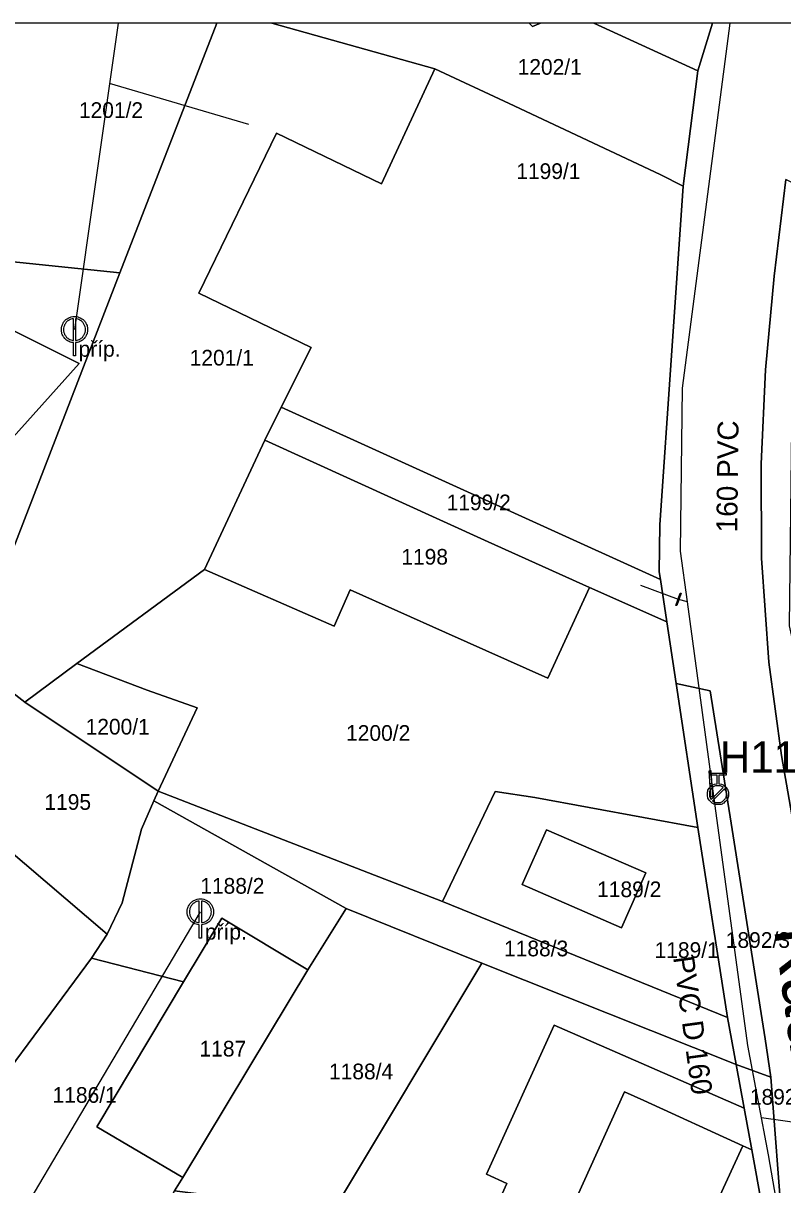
# Model space of a CAD drawing. Extents: x -559956 to -559707, y -1077221 to -1076919.
# Drawn here: x -559895.5 to -559822.9, y -1077029.9 to -1076918.8 of the extents above; entities that cross this region are included whole.
import ezdxf

# ---------------------------------------------------------------- set-up
doc = ezdxf.new("R2010")
doc.units = 0
for name, color, linetype in [('Armatura vodovodní', 7, 'Continuous'), ('Hydrant', 7, 'Continuous'), ('Kanalizační přípojka', 7, 'Continuous'), ('Kanalizační šachta', 7, 'Continuous'), ('Označení hydrantu', 7, 'Continuous'), ('Parcela-polygon', 7, 'Continuous'), ('Parcela-text', 7, 'Continuous'), ('Popis šachty', 7, 'Continuous'), ('Vodovodní přípojka', 7, 'Continuous'), ('Vodovodní řad', 7, 'Continuous'), ('Řad vodovodní označení', 7, 'Continuous'), ('Řad vodovodní popis', 7, 'Continuous')]:
    doc.layers.add(name, color=color, linetype=linetype)

msp = doc.modelspace()

# ---------------------------------------------------------------- linework, layer by layer
at = {"layer": 'Armatura vodovodní'}
for points in [[(-559832.58, -1076973.29), (-559832.99, -1076974.47), (-559833.07, -1076974.45), (-559832.66, -1076973.27), (-559832.58, -1076973.29)], [(-559829.74, -1076990.25), (-559829.57, -1076992.75), (-559829.72, -1076992.76), (-559829.89, -1076990.26), (-559829.74, -1076990.25)]]:
    msp.add_lwpolyline(points, dxfattribs=at)
at = {"layer": 'Hydrant'}
for points in [[(-559829.14, -1076991.5), (-559829.14, -1076990.69), (-559829.83, -1076990.69), (-559829.83, -1076990.5), (-559828.26, -1076990.5), (-559828.27, -1076990.69), (-559828.95, -1076990.69), (-559828.95, -1076991.51)], [(-559829.69, -1076993.01), (-559828.54, -1076991.86)], [(-559828.41, -1076992), (-559829.56, -1076993.14)]]:
    msp.add_lwpolyline(points, dxfattribs=at)
for points in [[(-559828.95, -1076991.51), (-559828.6, -1076991.54), (-559828.34, -1076991.8), (-559828.05, -1076992.09), (-559828.05, -1076992.5), (-559828.05, -1076992.92), (-559828.34, -1076993.21), (-559828.64, -1076993.5), (-559829.05, -1076993.5), (-559829.47, -1076993.5), (-559829.76, -1076993.21), (-559830.05, -1076992.92), (-559830.05, -1076992.5), (-559830.05, -1076992.09), (-559829.76, -1076991.79), (-559829.5, -1076991.53), (-559829.14, -1076991.5)], [(-559828.54, -1076991.86), (-559828.76, -1076991.69), (-559829.05, -1076991.69), (-559829.39, -1076991.69), (-559829.63, -1076991.92), (-559829.86, -1076992.16), (-559829.86, -1076992.5), (-559829.87, -1076992.79), (-559829.69, -1076993.01)], [(-559829.56, -1076993.14), (-559829.34, -1076993.31), (-559829.05, -1076993.31), (-559828.72, -1076993.31), (-559828.48, -1076993.08), (-559828.24, -1076992.84), (-559828.24, -1076992.5), (-559828.24, -1076992.21), (-559828.41, -1076992)]]:
    msp.add_open_spline(points, degree=3, dxfattribs=at)
at = {"layer": 'Kanalizační přípojka'}
for p, q in [((-559886.39, -1076918.77), (-559890.56, -1076948.07)), ((-559873.9, -1076928.46), (-559887.22, -1076924.55))]:
    msp.add_line(p, q, dxfattribs=at)
msp.add_lwpolyline([(-559908.57, -1077054.77), (-559908.02, -1077053.62), (-559878.53, -1077003.76)], dxfattribs=at)
at = {"layer": 'Kanalizační šachta'}
for points in [[(-559890.66, -1076949.11), (-559890.66, -1076947.04)], [(-559890.46, -1076947.04), (-559890.46, -1076949.11)], [(-559890.46, -1076949.32), (-559890.46, -1076950.57), (-559890.66, -1076950.57), (-559890.66, -1076949.32)], [(-559878.63, -1077004.79), (-559878.63, -1077002.72)], [(-559878.42, -1077002.72), (-559878.42, -1077004.79)], [(-559878.42, -1077005), (-559878.42, -1077006.26), (-559878.63, -1077006.26), (-559878.63, -1077005)]]:
    msp.add_lwpolyline(points, dxfattribs=at)
for points in [[(-559890.66, -1076949.32), (-559890.92, -1076949.3), (-559891.18, -1076949.16), (-559891.48, -1076948.99), (-559891.65, -1076948.7), (-559891.81, -1076948.4), (-559891.81, -1076948.07), (-559891.81, -1076947.75), (-559891.64, -1076947.45), (-559891.48, -1076947.15), (-559891.18, -1076946.99), (-559890.88, -1076946.82), (-559890.56, -1076946.82), (-559890.25, -1076946.82), (-559889.95, -1076946.99), (-559889.65, -1076947.15), (-559889.48, -1076947.45), (-559889.31, -1076947.75), (-559889.31, -1076948.07), (-559889.31, -1076948.4), (-559889.48, -1076948.7), (-559889.64, -1076948.99), (-559889.94, -1076949.16), (-559890.2, -1076949.3), (-559890.46, -1076949.32)], [(-559890.66, -1076947.04), (-559890.86, -1076947.05), (-559891.08, -1076947.17), (-559891.33, -1076947.3), (-559891.47, -1076947.55), (-559891.6, -1076947.8), (-559891.6, -1076948.07), (-559891.6, -1076948.34), (-559891.47, -1076948.59), (-559891.33, -1076948.84), (-559891.08, -1076948.97), (-559890.87, -1076949.09), (-559890.66, -1076949.11)], [(-559890.46, -1076949.11), (-559890.25, -1076949.09), (-559890.04, -1076948.97), (-559889.79, -1076948.84), (-559889.66, -1076948.59), (-559889.52, -1076948.34), (-559889.52, -1076948.07), (-559889.52, -1076947.8), (-559889.66, -1076947.55), (-559889.8, -1076947.3), (-559890.05, -1076947.17), (-559890.26, -1076947.05), (-559890.46, -1076947.04)], [(-559878.63, -1077005), (-559878.89, -1077004.99), (-559879.15, -1077004.84), (-559879.45, -1077004.68), (-559879.61, -1077004.38), (-559879.78, -1077004.08), (-559879.78, -1077003.76), (-559879.78, -1077003.43), (-559879.61, -1077003.13), (-559879.44, -1077002.83), (-559879.14, -1077002.67), (-559878.84, -1077002.51), (-559878.53, -1077002.51), (-559878.21, -1077002.51), (-559877.91, -1077002.67), (-559877.61, -1077002.83), (-559877.45, -1077003.13), (-559877.28, -1077003.43), (-559877.28, -1077003.76), (-559877.28, -1077004.08), (-559877.44, -1077004.38), (-559877.61, -1077004.68), (-559877.9, -1077004.84), (-559878.17, -1077004.99), (-559878.42, -1077005)], [(-559878.63, -1077002.72), (-559878.83, -1077002.74), (-559879.04, -1077002.85), (-559879.29, -1077002.99), (-559879.43, -1077003.24), (-559879.57, -1077003.49), (-559879.57, -1077003.76), (-559879.57, -1077004.03), (-559879.43, -1077004.27), (-559879.3, -1077004.52), (-559879.05, -1077004.66), (-559878.83, -1077004.78), (-559878.63, -1077004.79)], [(-559878.42, -1077004.79), (-559878.22, -1077004.78), (-559878, -1077004.66), (-559877.76, -1077004.52), (-559877.62, -1077004.27), (-559877.48, -1077004.03), (-559877.48, -1077003.76), (-559877.48, -1077003.49), (-559877.62, -1077003.24), (-559877.77, -1077002.99), (-559878.01, -1077002.85), (-559878.23, -1077002.74), (-559878.42, -1077002.72)]]:
    msp.add_open_spline(points, degree=3, dxfattribs=at)
at = {"layer": 'Parcela-polygon'}
for p, q in [((-559876.97, -1076918.77), (-559898.19, -1076918.77)), ((-559871.69, -1076918.77), (-559876.97, -1076918.77)), ((-559847.1, -1076918.77), (-559871.69, -1076918.77)), ((-559846.01, -1076918.77), (-559847.1, -1076918.77)), ((-559840.92, -1076918.77), (-559846.01, -1076918.77)), ((-559829.56, -1076918.77), (-559840.92, -1076918.77)), ((-559819.59, -1076918.77), (-559829.56, -1076918.77))]:
    msp.add_line(p, q, dxfattribs=at)
for points in [[(-559898.19, -1076918.77), (-559898.32, -1076921.1), (-559898.47, -1076923.82), (-559899.79, -1076923.81), (-559900.02, -1076928.91), (-559901.08, -1076931.24), (-559902.28, -1076931.69), (-559899.85, -1076941.23), (-559886.22, -1076942.65), (-559876.97, -1076918.77)], [(-559876.97, -1076918.77), (-559886.22, -1076942.65), (-559900.64, -1076979.86), (-559897.77, -1076981.82), (-559895.32, -1076983.7), (-559890.33, -1076980.02), (-559878.13, -1076971.03), (-559872.38, -1076958.66), (-559870.8, -1076955.49), (-559867.94, -1076949.78), (-559878.66, -1076944.59), (-559871.24, -1076929.28), (-559861.21, -1076934.12), (-559856.1, -1076923.13), (-559871.69, -1076918.77)], [(-559871.69, -1076918.77), (-559856.1, -1076923.13), (-559849.01, -1076926.45), (-559834.56, -1076933.23), (-559832.36, -1076934.35), (-559830.97, -1076923.33), (-559840.92, -1076918.77)], [(-559829.56, -1076918.77), (-559830.97, -1076923.33), (-559832.36, -1076934.35), (-559834.59, -1076966.73), (-559834.66, -1076971.24), (-559834.55, -1076971.98), (-559833.93, -1076976.03), (-559833.04, -1076981.92), (-559829.78, -1076982.61), (-559827.8, -1076995.29), (-559824.54, -1077015.89), (-559823.98, -1077019.58), (-559822.89, -1077034.16), (-559824.42, -1077051.06), (-559826.97, -1077064.1), (-559830.26, -1077074.01), (-559839.63, -1077092.62), (-559840.88, -1077095.88), (-559842.14, -1077099.15), (-559851.55, -1077116.77), (-559853.81, -1077121)], [(-559846.01, -1076918.77), (-559846.77, -1076919.08), (-559847.1, -1076918.77)], [(-559847.1, -1076918.77), (-559846.77, -1076919.08), (-559846.01, -1076918.77)], [(-559840.92, -1076918.77), (-559830.97, -1076923.33), (-559829.56, -1076918.77)], [(-559821.27, -1076998.68), (-559822.96, -1076988.81), (-559824.18, -1076979.89), (-559824.89, -1076969.92), (-559824.93, -1076960.91), (-559824.5, -1076951.91), (-559823.69, -1076942.95), (-559822.57, -1076933.71)], [(-559956.27, -1077016.3), (-559943.78, -1077017.51), (-559939.19, -1077016.99), (-559919.7, -1077011.48), (-559902.26, -1077026.17), (-559888.94, -1077008.18), (-559887.45, -1077005.89), (-559905.49, -1076990.5), (-559908.19, -1076992.6), (-559904.13, -1076996.96), (-559908.89, -1077001.4), (-559912.96, -1076997.07), (-559914.97, -1076999.06), (-559918.91, -1076994.86), (-559916.93, -1076992.9), (-559922.03, -1076987.42), (-559917.26, -1076982.87), (-559928.46, -1076979.86), (-559932.9, -1076984.41), (-559935.04, -1076986.85), (-559952.59, -1077008.71), (-559956.27, -1077013.67)]]:
    msp.add_lwpolyline(points, dxfattribs=at)
for points in [[(-559878.66, -1076944.59), (-559867.94, -1076949.78), (-559870.8, -1076955.49), (-559834.55, -1076971.98), (-559834.66, -1076971.24), (-559834.59, -1076966.73), (-559832.36, -1076934.35), (-559834.56, -1076933.23), (-559849.01, -1076926.45), (-559856.1, -1076923.13), (-559861.21, -1076934.12), (-559871.24, -1076929.28)], [(-559824.5, -1076951.91), (-559824.93, -1076960.91), (-559824.89, -1076969.92), (-559824.18, -1076979.89), (-559822.96, -1076988.81), (-559821.27, -1076998.68), (-559820.21, -1077004.57), (-559819.43, -1077009.52), (-559817.92, -1077019.93), (-559817.45, -1077021.39), (-559816.36, -1077023.11), (-559814.85, -1077024.48), (-559813.27, -1077025.59), (-559813.57, -1077021.42), (-559815.76, -1077006.35), (-559818.24, -1076994.33), (-559822.2, -1076976.41), (-559821.95, -1076954.78), (-559820.03, -1076934.98), (-559822.57, -1076933.71), (-559823.69, -1076942.95)], [(-559890.11, -1076951.3), (-559898.32, -1076947.22), (-559899.85, -1076941.23), (-559921.87, -1076938.92), (-559926.36, -1076967.89), (-559926.64, -1076971.53), (-559926.22, -1076975.34), (-559918.88, -1076975.14), (-559910.09, -1076973.59), (-559900.85, -1076963.28)], [(-559899.85, -1076941.23), (-559898.32, -1076947.22), (-559890.11, -1076951.3), (-559900.85, -1076963.28), (-559910.09, -1076973.59), (-559903.2, -1076978.11), (-559900.64, -1076979.86), (-559886.22, -1076942.65)], [(-559872.38, -1076958.66), (-559851.01, -1076968.36), (-559841.32, -1076972.75), (-559833.93, -1076976.03), (-559834.55, -1076971.98), (-559870.8, -1076955.49)], [(-559872.38, -1076958.66), (-559878.13, -1076971.03), (-559865.75, -1076976.42), (-559864.21, -1076972.95), (-559855.09, -1076977.03), (-559845.31, -1076981.41), (-559841.32, -1076972.75), (-559851.01, -1076968.36)], [(-559882.57, -1076992.23), (-559862.47, -1077000.01), (-559855.37, -1077002.76), (-559850.36, -1076992.26), (-559846.56, -1076992.82), (-559830.96, -1076995.7), (-559833.04, -1076981.92), (-559833.93, -1076976.03), (-559841.32, -1076972.75), (-559845.31, -1076981.41), (-559855.09, -1076977.03), (-559864.21, -1076972.95), (-559865.75, -1076976.42), (-559878.13, -1076971.03), (-559890.33, -1076980.02), (-559883.6, -1076982.55), (-559878.83, -1076984.23)], [(-559878.83, -1076984.23), (-559883.6, -1076982.55), (-559890.33, -1076980.02), (-559895.32, -1076983.7), (-559882.57, -1076992.23)], [(-559895.32, -1076983.7), (-559897.77, -1076981.82), (-559905.49, -1076990.5), (-559887.45, -1077005.89), (-559885.99, -1077002.89), (-559884.16, -1076995.84), (-559882.97, -1076993.14), (-559882.57, -1076992.23)], [(-559823.98, -1077019.58), (-559824.54, -1077015.89), (-559827.8, -1076995.29), (-559829.78, -1076982.61), (-559833.04, -1076981.92), (-559830.96, -1076995.7), (-559828.13, -1077013.85), (-559827.3, -1077018.35)], [(-559855.37, -1077002.76), (-559862.47, -1077000.01), (-559882.57, -1076992.23), (-559882.97, -1076993.14), (-559864.6, -1077003.43), (-559851.62, -1077008.67), (-559827.3, -1077018.35), (-559828.13, -1077013.85)], [(-559830.96, -1076995.7), (-559846.56, -1076992.82), (-559850.36, -1076992.26), (-559855.37, -1077002.76), (-559828.13, -1077013.85)], [(-559884.16, -1076995.84), (-559885.99, -1077002.89), (-559887.45, -1077005.89), (-559888.94, -1077008.18), (-559880.14, -1077010.46), (-559876.49, -1077004.36), (-559868.25, -1077009.31), (-559864.6, -1077003.43), (-559882.97, -1076993.14)], [(-559847.76, -1077001.14), (-559838.28, -1077005.29), (-559835.95, -1077000.03), (-559845.45, -1076995.9)], [(-559835.95, -1077000.03), (-559838.28, -1077005.29), (-559847.76, -1077001.14), (-559845.45, -1076995.9)], [(-559871.91, -1077015.38), (-559880.21, -1077029.16), (-559880.99, -1077030.45), (-559865.8, -1077032.33), (-559851.62, -1077008.67), (-559864.6, -1077003.43), (-559868.25, -1077009.31)], [(-559876.49, -1077004.36), (-559880.14, -1077010.46), (-559888.42, -1077024.31), (-559880.21, -1077029.16), (-559871.91, -1077015.38), (-559868.25, -1077009.31)], [(-559888.94, -1077008.18), (-559902.26, -1077026.17), (-559897.39, -1077030), (-559899.67, -1077032.65), (-559890.87, -1077039.51), (-559889.51, -1077037.9), (-559886.76, -1077034.59), (-559883.82, -1077031.07), (-559882.16, -1077032.46), (-559880.99, -1077030.45), (-559880.21, -1077029.16), (-559888.42, -1077024.31), (-559880.14, -1077010.46)], [(-559851.19, -1077028.84), (-559846.79, -1077019.15), (-559844.72, -1077014.6), (-559826.54, -1077022.53), (-559827.3, -1077018.35), (-559851.62, -1077008.67), (-559865.8, -1077032.33), (-559880.99, -1077030.45), (-559882.16, -1077032.46), (-559856.03, -1077054.13), (-559852.74, -1077037.52), (-559849.23, -1077029.74)], [(-559844.72, -1077014.6), (-559846.79, -1077019.15), (-559851.19, -1077028.84), (-559849.23, -1077029.74), (-559852.74, -1077037.52), (-559856.03, -1077054.13), (-559859.59, -1077058.36), (-559855.38, -1077061.9), (-559852.72, -1077054.42), (-559851.42, -1077055.1), (-559843.19, -1077037.18), (-559842.18, -1077034.99), (-559841.49, -1077033.13), (-559843.15, -1077032.38), (-559837.99, -1077020.96), (-559836.12, -1077021.81), (-559826.67, -1077026.12), (-559825.81, -1077026.51), (-559826.54, -1077022.53)], [(-559827.3, -1077018.35), (-559826.54, -1077022.53), (-559825.81, -1077026.51), (-559824.81, -1077031.97), (-559822.89, -1077034.16), (-559823.98, -1077019.58)], [(-559843.19, -1077037.18), (-559833.75, -1077041.51), (-559832.73, -1077039.29), (-559826.67, -1077026.12), (-559836.12, -1077021.81), (-559837.99, -1077020.96), (-559843.15, -1077032.38), (-559841.49, -1077033.13), (-559842.18, -1077034.99)], [(-559826.67, -1077026.12), (-559832.73, -1077039.29), (-559833.75, -1077041.51), (-559826.26, -1077044.95), (-559825.83, -1077041.69), (-559824.81, -1077031.97), (-559825.81, -1077026.51)]]:
    msp.add_lwpolyline(points, close=True, dxfattribs=at)
at = {"layer": 'Vodovodní přípojka'}
for p, q in [((-559829.73, -1076991.5), (-559829.89, -1076991.51)), ((-559829.6, -1076991.5), (-559829.73, -1076991.5)), ((-559824.88, -1077023.43), (-559812.21, -1077025.22))]:
    msp.add_line(p, q, dxfattribs=at)
msp.add_lwpolyline([(-559831.97, -1076974.12), (-559832.83, -1076973.87), (-559836.43, -1076972.56)], dxfattribs=at)
at = {"layer": 'Vodovodní řad'}
for points in [[(-559831.97, -1076974.12), (-559832.63, -1076969.27), (-559832.43, -1076953.68), (-559827.88, -1076918.77)], [(-559823.2, -1077033.07), (-559823.2, -1077032.9), (-559824.21, -1077026.98), (-559826.19, -1077016.54), (-559829.6, -1076991.5), (-559831.97, -1076974.12)]]:
    msp.add_lwpolyline(points, dxfattribs=at)

# ---------------------------------------------------------------- texts
at = {"layer": 'Označení hydrantu'}
msp.add_text('H11', height=3, dxfattribs=at).set_placement((-559828.86, -1076990.46))
at = {"layer": 'Parcela-text'}
for s, p in [('1202/1', (-559848.2, -1076923.7)), ('1201/2', (-559890.14, -1076927.83)), ('1199/1', (-559848.33, -1076933.67)), ('1201/1', (-559879.55, -1076951.51)), ('1199/2', (-559854.99, -1076965.35)), ('1198', (-559859.32, -1076970.55)), ('1200/1', (-559889.5, -1076986.8)), ('1200/2', (-559864.6, -1076987.4)), ('1195', (-559893.44, -1076994)), ('1188/2', (-559878.54, -1077002.02)), ('1189/2', (-559840.6, -1077002.35)), ('1892/3', (-559828.3, -1077007.2)), ('1188/3', (-559849.5, -1077008.01)), ('1189/1', (-559835.11, -1077008.16)), ('1187', (-559878.61, -1077017.59)), ('1188/4', (-559866.23, -1077019.77)), ('1186/1', (-559892.66, -1077022.02)), ('1892/5', (-559826, -1077022.2))]:
    msp.add_text(s, height=1.5, dxfattribs=at).set_placement(p)
at = {"layer": 'Popis šachty'}
for p in [(-559890.17, -1076950.67), (-559878.1, -1077006.41)]:
    msp.add_text('příp.', height=1.5, dxfattribs=at).set_placement(p)
at = {"layer": 'Řad vodovodní označení'}
msp.add_text('Řad 1-3', height=5, rotation=277.7613, dxfattribs=at).set_placement((-559823.7, -1077005.38))
at = {"layer": 'Řad vodovodní popis'}
for s, rotation, p in [(' 160 PVC', 89.2576, (-559827.22, -1076968.22)), ('PVC D 160', 277.7611, (-559833.34, -1077008.1))]:
    msp.add_text(s, height=2, rotation=rotation, dxfattribs=at).set_placement(p)

doc.saveas('drawing.dxf')
